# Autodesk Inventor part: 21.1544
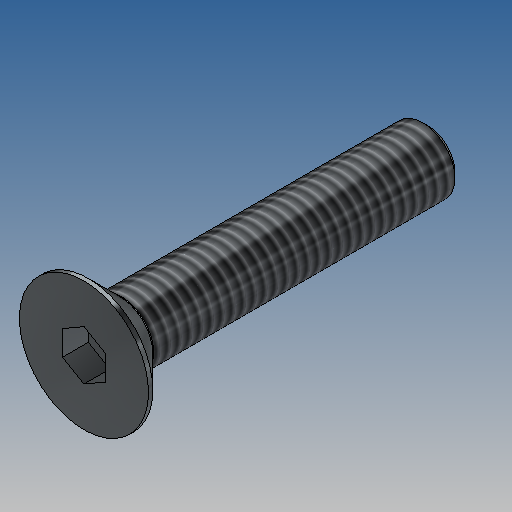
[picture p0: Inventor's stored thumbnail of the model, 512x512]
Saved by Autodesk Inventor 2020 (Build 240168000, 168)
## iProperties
Created: 2007-03
Part Number: 21.1544
Material: Steel, Mild
Description: M3x16 CSUNK
Document SubType Name: Modeling
Standard: DIN 7991
Designer: Andy Moles
Standards Organization: DIN
Language: en-US
Size Designation: M3x8
Categories: <MemberInstance Version="R10.0.0"><Categories><Category DisplayName="Fasteners" InternalName="e4da775c-781d-43d5-af7c-5136215cf5a6" Mnemonic="FSTN"><Category Di
Density: 7.85 g/cm^3
Mass: 0.997284 g
Surface Area: 2.10689 cm^2
Volume: 0.127043 cm^3
Appearance: Zinc
Author: Andy Moles
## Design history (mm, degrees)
node "Sketch1"
node "WorkPoint1"
sketch "Sketch2"
  geometry: L1 (-1.5, -16)-(0, -16); L2 (-1.5, -1.7)-(-1.5, -16); L3 (-3, -0.2)-(-1.5, -1.7); L4 (-3, 0)-(-3, -0.2); L5 (0, 0)-(-3, 0); L6 (0, -16)-(0, 0); L7 (0, -16)-(0, 0); L8 (0, -8.8)-(0, 2.4) reference; L9 (0.3, 0)-(-3.9, 0) reference
  constraints: 14 end point, 3 vertical, 2 horizontal
  dimensions: "d1" = 45 deg angle of L3 L6; "d3" = 3 distance of L5.start L4.start (= 0.5 x dk); "d5" = 1.5 distance of L1.start L1.end (= 0.5 x NND); "d7" = 16 distance of L1.end L5.start (= NLG); "ParC" = 0.2 distance of L4.start L3.start; "d22" = 0 distance between parallel lines of L8 L6; "d23" = 0 distance between parallel lines of L9 L5
fillet "Fillet1" dims "d18" = 0.1 (= r)
chamfer "Chamfer1" distance "d19" = 0.25 (= 0.5 x PTC); stored, may be unused: angle "d20" = 45 deg, second distance "d39" = 0.25 (= 0.5 x PTC)
node "MSC_A1"
node "MSC_PF1"
node "MSC_PT1"
body "Solid1"
revolve "Revolution1" stored, may be unused: angle "d8" = 360 deg
sketch "Sketch3"
  geometry: L1 (-1, 0.577)-(-1, -0.577); L2 (0, 1.155)-(-1, 0.577); L3 (1, 0.577)-(0, 1.155); L4 (1, -0.577)-(1, 0.577); L5 (0, -1.155)-(1, -0.577); L6 (-1, -0.577)-(0, -1.155); C1 r 1 at (0, 0); C2 r 1.5 at (0, 0) reference
  constraints: 12 end point, 6 tangent, 2 parallel, 2 vertical, 1 centre point, 1 concentric
  dimensions: "d11" = 2 diameter of C1 (= ParS); "d13" = 120 deg angle of L1 L2; "d15" = 120 deg angle of L6 L1
extrude "Extrusion1" cut sketch "Sketch3" distance "d16" = 1.2 (= ParT); taper "d17" = 0 deg
thread "Thread1" dims "d35" = 0, "b" = 14
other parameters: "NND" = 3 [user parameter; used in 2 equation terms], "PTC" = 0.5 [user parameter; used in 2 equation terms], "dk" = 6 [user parameter; used in 1 equation term], "ParK" = 1.7 [user parameter], "ParS" = 2 [user parameter; used in 1 equation term], "ParT" = 1.2 [user parameter; used in 1 equation term], "r" = 0.1 [user parameter; used in 1 equation term], "NLG" = 16 [user parameter; used in 1 equation term], "d0" = 45 deg (derived), "d2" = 3 (derived), "d4" = 1.5 (derived), "d6" = 8 (derived), "d9" = 0, "d10" = 2 (derived), "d12" = 120 deg (derived), "d14" = 120 deg (derived), "d37" = 0, "d38" = 0, "d40" = 0, "d41" = 0, "d42" = 0, "THREADDIA" = 3 (= NND) [user parameter]
